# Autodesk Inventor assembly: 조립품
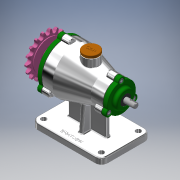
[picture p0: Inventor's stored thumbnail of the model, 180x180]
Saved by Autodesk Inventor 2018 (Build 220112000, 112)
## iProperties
Created: 2020-03
Part Number: 조립품
Document SubType Name: Assembly
Designer: Administrator
Author: Administrator
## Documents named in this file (15)
- C:\Users\Administrator\Desktop\700306V1014\조립품.iam
- C:\Users\Administrator\Desktop\700306V1014\본체.ipt
- C:\Users\Administrator\Desktop\700306V1014\개스킷 A.ipt
- C:\Users\Administrator\Desktop\700306V1014\개스킷 B.ipt
- C:\Users\Administrator\Desktop\700306V1014\앞커버.ipt
- C:\Users\Administrator\Desktop\700306V1014\뒤커버.ipt
- C:\Users\Administrator\Desktop\700306V1014\베어링 6203.ipt
- C:\Users\Administrator\Desktop\700306V1014\베어링 6200.ipt
- C:\Users\Administrator\Desktop\700306V1014\축.ipt
- C:\Users\Administrator\Desktop\700306V1014\키 4x4x14.ipt
- C:\Users\Administrator\Desktop\700306V1014\스프로킷.ipt
- C:\Users\Administrator\Desktop\700306V1014\오일 실 17 30 8.ipt
- C:\Users\Administrator\Desktop\700306V1014\오일 실 10 20 7.ipt
- C:\Users\Administrator\Desktop\700306V1014\마개.ipt
- C:\Users\Administrator\Desktop\700306V1014\볼트 M5.ipt
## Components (2 placed, 2 different names)
1. 개스킷 A:1
2. 개스킷 B:1
